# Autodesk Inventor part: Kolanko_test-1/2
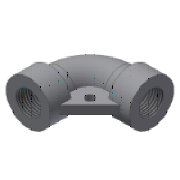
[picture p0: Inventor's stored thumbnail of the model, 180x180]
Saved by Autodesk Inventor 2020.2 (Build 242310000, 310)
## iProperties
Manager: www.cadconsulting.pl
Company: Fabian Stasiak CAD Consulting
Created: 2014-08
Part Number: Kolanko_test-1/2
Material: Ogólny
Document SubType Name: Modeling
Standard: ANSI
Designer: F.Stasiak
Language: pl-PL
Size Designation: 1/2
Categories: <MemberInstance><Categories><Category DisplayName="Rury cienko- i grubościenne" InternalName="4347fa0f-2144-441d-94cd-e3e15c92b736" Mnemonic="TUBEANDPIPE"><Cate
Density: 1 g/cm^3
Appearance: Domyślna
Catalog Web Link: www.expertbooks.pl
IsCustomPart: 0
Author: F.Stasiak
Subject: Zbiór ćwiczeń. Autodesk Inventor 2020. Kurs Professional
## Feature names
1. Przeciągnięcie1
2. Wyciągnięcie proste1 [Extrusion]
3. Wyciągnięcie proste2 [Extrusion]
4. Wyciągnięcie proste5 [Extrusion]
## Parameters: d0 = 45.7835 mm, d1 = 45.7835 mm, d2 = 22.89175 mm, d4 = 0, d5 = 0, d6 = 33.02 mm, d7 = 18.3134 mm, d9 = 15.748 mm, d10 = 0, d11 = 33.02 mm, d12 = 15.748 mm, d13 = 0, d19 = 19.8628 mm, d20 = 0, d21 = 19.8628 mm, d22 = 0, ID = 18.3134 mm, OD = 33.02 mm, GL = 15.748 mm, G = 3.175 mm, d23 = 3.175 mm, d24 = 6.35 mm, d26 = 6.35 mm, d27 = 0
